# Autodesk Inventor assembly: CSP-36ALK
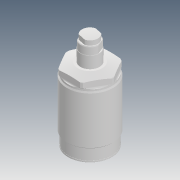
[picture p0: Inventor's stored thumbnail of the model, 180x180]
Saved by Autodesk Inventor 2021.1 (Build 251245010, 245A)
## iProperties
Created: 2019-01
Part Number: CSP-36ALK
Description: STEP AP203
Document SubType Name: Assembly
Designer: user
Title: CSP-36ALK.STEP
Revision Number: ÈÎºÎ
Sending System: SolidWorks 2014
Preprocessor: SwSTEP 2.0
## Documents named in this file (4)
- D:\Vault_2016\Projekty\Clamptek\Hydraulic\CSP-P-K\CSP-36KP\Inventor\CSP-36ALK\CSP-36ALK.iam
- D:\Vault_2016\Projekty\Clamptek\Hydraulic\CSP-P-K\CSP-36KP\Inventor\CSP-36ALK\CSP-036-K±¾Ìå£¨ÉÏÉý£©.ipt
- D:\Vault_2016\Projekty\Clamptek\Hydraulic\CSP-P-K\CSP-36KP\Inventor\CSP-36ALK\CSP-036»îÈû¸Ë.ipt
- D:\Vault_2016\Projekty\Clamptek\Hydraulic\CSP-P-K\CSP-36KP\Inventor\CSP-36ALK\CSP-036Ô²Í·ÂÝË¨.ipt
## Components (3 placed, 3 different names)
1. CSP-036-K±¾Ìå£¨ÉÏÉý£©_1
2. CSP-036»îÈû¸Ë_2
3. CSP-036Ô²Í·ÂÝË¨_3
